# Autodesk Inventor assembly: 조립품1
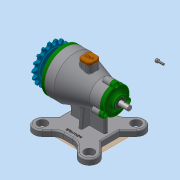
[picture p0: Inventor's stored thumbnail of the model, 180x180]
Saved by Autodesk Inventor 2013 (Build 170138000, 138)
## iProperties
Created: 2018-03
Part Number: 조립품1
Document SubType Name: Assembly
Designer: dgall
Author: dgall
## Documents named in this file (15)
- C:\Users\dgall\Desktop\480307V1029\조립품1.iam
- C:\Users\dgall\Desktop\480307V1029\뒤커버.ipt
- C:\Users\dgall\Desktop\480307V1029\마개.ipt
- C:\Users\dgall\Desktop\480307V1029\베어링-6200.ipt
- C:\Users\dgall\Desktop\480307V1029\베어링-6203.ipt
- C:\Users\dgall\Desktop\480307V1029\본체1.ipt
- C:\Users\dgall\Desktop\480307V1029\볼트 M4 x 12.ipt
- 볼트 M4 x 12.ipt
- C:\Users\dgall\Desktop\480307V1029\스프로킷.ipt
- C:\Users\dgall\Desktop\480307V1029\앞커버.ipt
- C:\Users\dgall\Desktop\480307V1029\오일 실 10 20 7.ipt
- C:\Users\dgall\Desktop\480307V1029\오일 실 17 30 8.ipt
- C:\Users\dgall\Desktop\480307V1029\축.ipt
- C:\Users\dgall\Desktop\480307V1029\키 5 x 5.ipt
- 키 5 x 5.ipt
